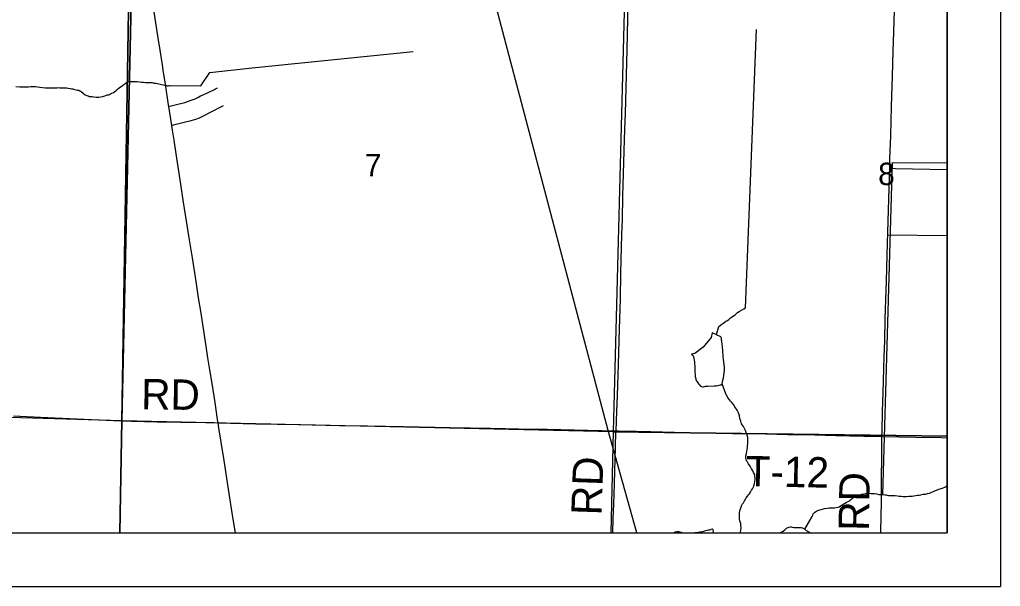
# Model space of a CAD drawing. Extents: x 0 to 34, y 0 to 22.
# Drawn here: x 7.163 to 9, y 14 to 15.061 of the extents above; entities that cross this region are included whole.
import ezdxf

# ---------------------------------------------------------------- set-up
doc = ezdxf.new("R2010")
doc.units = 0
for name, color, linetype in [('Default', 7, 'Continuous'), ('GM_X_Minor_Lake', 7, 'Continuous'), ('GM_X_Minor_River', 7, 'Continuous'), ('GM_X_Rail_Line', 7, 'Continuous'), ('GM_X_Section', 7, 'Continuous'), ('GM_X_Section_Text', 7, 'Continuous'), ('GM_X_State_Route', 7, 'Continuous'), ('GM_X_Township_Road', 7, 'Continuous'), ('GM_X_Township_Road_Text', 7, 'Continuous'), ('SH_Data', 7, 'Continuous')]:
    doc.layers.add(name, color=color, linetype=linetype)

msp = doc.modelspace()

# ---------------------------------------------------------------- linework, layer by layer
at = {"layer": 'Default'}
for points in [[(8.9, 14.2811), (8.9, 15.2832), (8.3007, 15.2901), (8.2749, 14.2894)], [(8.2702, 14.1), (8.9, 14.1), (8.9, 14.2811), (8.2749, 14.2894)]]:
    msp.add_lwpolyline(points, close=True, dxfattribs=at)
at = {"layer": 'GM_X_Minor_Lake'}
for points in [[(8.46, 14.4747), (8.4583, 14.4656), (8.4431, 14.4481), (8.4279, 14.4362), (8.4214, 14.4345), (8.4241, 14.4329), (8.4251, 14.4294), (8.4258, 14.4264), (8.4261, 14.4233), (8.4269, 14.4206), (8.4268, 14.4183), (8.4271, 14.4164), (8.4274, 14.413), (8.4274, 14.4096), (8.4273, 14.4065), (8.4276, 14.4039), (8.4279, 14.4008), (8.4282, 14.3962), (8.4285, 14.3924), (8.4292, 14.3894), (8.4296, 14.3871), (8.4299, 14.3851), (8.4321, 14.3828), (8.4343, 14.379), (8.4362, 14.3774), (8.4377, 14.3755), (8.4399, 14.3743), (8.4418, 14.3735), (8.4441, 14.3738), (8.4476, 14.3745), (8.4518, 14.3748), (8.464, 14.3752)], [(8.46, 14.4747), (8.4583, 14.4656), (8.4431, 14.4481), (8.4279, 14.4362), (8.4214, 14.4345), (8.4241, 14.4329), (8.4251, 14.4294), (8.4258, 14.4264), (8.4261, 14.4233), (8.4269, 14.4206), (8.4268, 14.4183), (8.4271, 14.4164), (8.4274, 14.413), (8.4274, 14.4096), (8.4273, 14.4065), (8.4276, 14.4039), (8.4279, 14.4008), (8.4282, 14.3962), (8.4285, 14.3924), (8.4292, 14.3894), (8.4296, 14.3871), (8.4299, 14.3851), (8.4321, 14.3828), (8.4343, 14.379), (8.4362, 14.3774), (8.4377, 14.3755), (8.4399, 14.3743), (8.4418, 14.3735), (8.4441, 14.3738), (8.4476, 14.3745), (8.4518, 14.3748), (8.464, 14.3752), (8.4678, 14.3755), (8.4712, 14.3758), (8.4735, 14.3766), (8.4762, 14.3773), (8.4785, 14.3791), (8.4798, 14.3863), (8.481, 14.3905), (8.4819, 14.395), (8.4824, 14.4003), (8.4829, 14.4045), (8.483, 14.4095), (8.4827, 14.4152), (8.482, 14.4198), (8.4814, 14.4251), (8.4808, 14.4305), (8.4805, 14.435), (8.4802, 14.4385), (8.4798, 14.4411), (8.4799, 14.4434), (8.4796, 14.4457), (8.4796, 14.448), (8.4793, 14.4503), (8.4789, 14.4526), (8.4786, 14.4549), (8.4783, 14.4572), (8.4779, 14.4591), (8.4776, 14.461), (8.4776, 14.4629), (8.4773, 14.4648), (8.4766, 14.4671), (8.46, 14.4747)], [(8.464, 14.3752), (8.4678, 14.3755), (8.4712, 14.3758), (8.4735, 14.3766), (8.4762, 14.3773), (8.4785, 14.3791), (8.4798, 14.3863), (8.481, 14.3905), (8.4819, 14.395), (8.4824, 14.4003), (8.4829, 14.4045), (8.483, 14.4095), (8.4827, 14.4152), (8.482, 14.4198), (8.4814, 14.4251), (8.4808, 14.4305), (8.4805, 14.435), (8.4802, 14.4385), (8.4798, 14.4411), (8.4799, 14.4434), (8.4796, 14.4457), (8.4796, 14.448), (8.4793, 14.4503), (8.4789, 14.4526), (8.4786, 14.4549), (8.4783, 14.4572), (8.4779, 14.4591), (8.4776, 14.461), (8.4776, 14.4629), (8.4773, 14.4648), (8.4766, 14.4671), (8.46, 14.4747)], [(8.3881, 14.1), (8.3884, 14.1005), (8.3907, 14.102), (8.3938, 14.1027), (8.3968, 14.1026), (8.3991, 14.1022), (8.4021, 14.1014), (8.4047, 14.1)], [(8.4618, 14.1), (8.4619, 14.1004), (8.4623, 14.1035), (8.462, 14.1061), (8.4601, 14.1069), (8.4574, 14.1062), (8.4548, 14.1055), (8.4529, 14.1052), (8.4509, 14.1045), (8.4483, 14.1038), (8.4456, 14.1031), (8.4437, 14.1027), (8.4417, 14.1024), (8.4391, 14.1017), (8.4368, 14.1014), (8.4337, 14.1007), (8.4299, 14.1004), (8.4278, 14.1)]]:
    msp.add_lwpolyline(points, dxfattribs=at)
at = {"layer": 'GM_X_Minor_River'}
msp.add_line((8.7886, 14.6579), (8.9, 14.6566), dxfattribs=at)
for points in [[(8.5226, 14.5216), (8.5433, 15.0424)], [(7.4448, 14.9375), (7.5023, 14.937), (7.5192, 14.9621), (7.5986, 14.9706), (7.9, 15.0012)], [(7.2774, 14.9271), (7.2822, 14.9224), (7.2856, 14.9201), (7.2886, 14.9189), (7.2913, 14.918), (7.2932, 14.9172), (7.2958, 14.9172), (7.2985, 14.9171), (7.3019, 14.9167), (7.3061, 14.9158), (7.311, 14.9157), (7.3141, 14.9164), (7.3187, 14.9171), (7.3221, 14.9185), (7.3244, 14.9192), (7.3267, 14.9199), (7.329, 14.9203), (7.3309, 14.921), (7.3332, 14.9221), (7.3356, 14.9232), (7.3383, 14.9246), (7.341, 14.9265), (7.3433, 14.9283), (7.346, 14.9309), (7.3495, 14.9335), (7.3518, 14.9354), (7.3549, 14.9368), (7.358, 14.9394), (7.3615, 14.942), (7.3634, 14.9439), (7.3676, 14.9449), (7.3714, 14.9452), (7.3749, 14.9451), (7.3775, 14.9451), (7.3798, 14.945), (7.3832, 14.9449), (7.387, 14.9445), (7.3912, 14.944), (7.395, 14.9439), (7.3984, 14.9435), (7.4019, 14.9434), (7.4068, 14.9433), (7.411, 14.9432), (7.4148, 14.9423), (7.4182, 14.9423), (7.4209, 14.9414), (7.4288, 14.9397), (7.4315, 14.9389), (7.4345, 14.9385), (7.4368, 14.938), (7.4394, 14.9372), (7.4417, 14.9372), (7.4433, 14.9375), (7.4448, 14.9375)], [(7.1557, 14.9355), (7.1629, 14.9354), (7.1683, 14.9352), (7.174, 14.9351), (7.1793, 14.9354), (7.1835, 14.9357), (7.1877, 14.936), (7.1923, 14.9355), (7.1964, 14.935), (7.2006, 14.9345), (7.2055, 14.9337), (7.2109, 14.9332), (7.2162, 14.933), (7.22, 14.9333), (7.2246, 14.9332), (7.2291, 14.9331), (7.233, 14.9334), (7.2353, 14.9338), (7.2379, 14.9333), (7.241, 14.9332), (7.244, 14.9332), (7.2474, 14.9331), (7.2512, 14.933), (7.2539, 14.9326), (7.2573, 14.9321), (7.26, 14.9317), (7.2626, 14.9312), (7.2656, 14.93), (7.2687, 14.9296), (7.2713, 14.9291), (7.2736, 14.9287), (7.2755, 14.9279), (7.2774, 14.9271)], [(8.7795, 14.1721), (8.7977, 14.7937), (8.9, 14.7928)], [(8.468, 14.4716), (8.4728, 14.4866), (8.4779, 14.4907), (8.4821, 14.4936), (8.4856, 14.4962), (8.4887, 14.498), (8.4914, 14.4999), (8.4945, 14.5025), (8.4976, 14.5047), (8.4999, 14.5065), (8.5034, 14.5084), (8.5053, 14.5102), (8.5076, 14.5125), (8.5107, 14.5147), (8.5196, 14.5194), (8.5223, 14.5213), (8.5226, 14.5216)], [(8.513, 14.1), (8.5133, 14.1012), (8.5142, 14.1091), (8.514, 14.1149), (8.5137, 14.1179), (8.5126, 14.121), (8.5119, 14.1229), (8.5112, 14.1267), (8.5113, 14.1305), (8.5114, 14.1343), (8.5114, 14.1374), (8.5119, 14.1412), (8.5131, 14.145), (8.5151, 14.1506), (8.5171, 14.1544), (8.5187, 14.1563), (8.5207, 14.16), (8.5219, 14.1623), (8.5238, 14.1657), (8.5262, 14.1686), (8.5281, 14.1713), (8.5301, 14.1735), (8.5317, 14.1765), (8.5337, 14.1799), (8.5356, 14.1825), (8.5368, 14.1848), (8.538, 14.1874), (8.5388, 14.1897), (8.5393, 14.1923), (8.5397, 14.1961), (8.5406, 14.1999), (8.5403, 14.2079), (8.5396, 14.2098), (8.5378, 14.2129), (8.5363, 14.216), (8.5338, 14.2203), (8.5312, 14.2253), (8.5282, 14.2295), (8.526, 14.233), (8.5246, 14.2353), (8.5235, 14.2384), (8.5232, 14.2414), (8.5232, 14.2445), (8.5241, 14.249), (8.5249, 14.2524), (8.5258, 14.2562), (8.5262, 14.2596), (8.5263, 14.2634), (8.5268, 14.2669), (8.5272, 14.2699), (8.5269, 14.2733), (8.5266, 14.2779), (8.5256, 14.2836), (8.5238, 14.2882), (8.5223, 14.2921), (8.5205, 14.2955), (8.5187, 14.299), (8.5168, 14.3017), (8.515, 14.3044), (8.5136, 14.3094), (8.5122, 14.3144), (8.5111, 14.319), (8.5093, 14.3247), (8.5068, 14.3301), (8.5027, 14.3359), (8.4998, 14.3406), (8.4972, 14.344), (8.4946, 14.3468), (8.4927, 14.3491), (8.4909, 14.3514), (8.4894, 14.3534), (8.4868, 14.358), (8.4854, 14.3607), (8.4785, 14.3791)], [(8.6334, 14.1068), (8.6472, 14.1305), (8.6484, 14.1332), (8.6492, 14.1358), (8.6516, 14.138), (8.6543, 14.1399), (8.6581, 14.1421), (8.662, 14.1431), (8.6666, 14.1445), (8.6708, 14.1456), (8.6754, 14.1463), (8.6792, 14.1469), (8.6818, 14.1469), (8.6845, 14.1468), (8.6868, 14.1468), (8.6895, 14.1471), (8.6925, 14.1474), (8.6952, 14.1481), (8.6979, 14.1492), (8.7006, 14.1506), (8.7029, 14.1521), (8.7052, 14.1536), (8.7079, 14.155), (8.711, 14.1569), (8.7133, 14.1583), (8.716, 14.1594), (8.7179, 14.1609), (8.7199, 14.1624), (8.7218, 14.1639), (8.7238, 14.1657), (8.7257, 14.1672), (8.7276, 14.1687), (8.7295, 14.1694), (8.7326, 14.1705), (8.7349, 14.1712), (8.7384, 14.1719), (8.7403, 14.1726), (8.7475, 14.1736), (8.7502, 14.1739), (8.754, 14.1742), (8.7571, 14.1741), (8.7601, 14.174), (8.7639, 14.1736), (8.7677, 14.1731), (8.7726, 14.1722), (8.7795, 14.1721), (8.7833, 14.1716), (8.7859, 14.1715), (8.7882, 14.1707), (8.7901, 14.1703), (8.7935, 14.1702), (8.7977, 14.1701), (8.8027, 14.17), (8.8072, 14.1692), (8.8106, 14.1687), (8.8141, 14.1686), (8.8179, 14.1682), (8.8209, 14.1681), (8.8243, 14.1684), (8.8285, 14.1687), (8.832, 14.1686), (8.835, 14.1689), (8.8377, 14.1696), (8.8415, 14.1703), (8.8446, 14.1706), (8.8476, 14.1709), (8.8511, 14.1716), (8.8553, 14.1723), (8.8576, 14.1726), (8.8599, 14.1729), (8.8633, 14.1736), (8.8675, 14.1747), (8.8717, 14.1765), (8.8775, 14.179), (8.8848, 14.1819), (8.8917, 14.184), (8.8971, 14.1866), (8.9, 14.188)], [(8.5874, 14.1), (8.5883, 14.101), (8.5929, 14.1036), (8.596, 14.1058), (8.5995, 14.1087), (8.6034, 14.1106), (8.6064, 14.1113), (8.6083, 14.1112), (8.6102, 14.1108), (8.6129, 14.1103), (8.6156, 14.1103), (8.6178, 14.1102), (8.6205, 14.1102), (8.6239, 14.1101), (8.627, 14.11), (8.6293, 14.1096), (8.6334, 14.1068), (8.6364, 14.1049), (8.6398, 14.1029), (8.6428, 14.1009), (8.6436, 14.1)]]:
    msp.add_lwpolyline(points, dxfattribs=at)
at = {"layer": 'GM_X_Rail_Line'}
msp.add_lwpolyline([(8.3191, 14.1), (8.2652, 14.2915), (7.9984, 15.3006), (7.7787, 16.1186), (7.5464, 16.952), (7.4475, 17.3725), (7.3986, 17.4999), (7.3389, 17.6382), (7.2697, 17.7778), (7.0716, 18.0894), (7.0417, 18.1342), (7.0105, 18.1626), (6.978, 18.1748), (6.9427, 18.181)], dxfattribs=at)
at = {"layer": 'GM_X_Section'}
for points in [[(6.3631, 15.3454), (7.3704, 15.3088), (7.3544, 14.3098), (6.3444, 14.34)], [(7.3704, 15.3088), (8.3007, 15.2901), (8.2749, 14.2894), (7.3544, 14.3098)]]:
    msp.add_lwpolyline(points, close=True, dxfattribs=at)
at = {"layer": 'GM_X_State_Route'}
msp.add_lwpolyline([(7.4137, 15.0791), (7.4213, 15.0306), (7.4251, 15.0035), (7.4295, 14.9765), (7.4317, 14.9618), (7.4352, 14.9403), (7.4412, 14.9016), (7.4417, 14.8983), (7.4471, 14.8629), (7.4484, 14.8543), (7.4514, 14.8352), (7.4551, 14.81), (7.4642, 14.7529), (7.4687, 14.7228), (7.4761, 14.6761), (7.4798, 14.6522), (7.4858, 14.6153), (7.4928, 14.5705), (7.4974, 14.5404), (7.5016, 14.5153), (7.5115, 14.4495), (7.5148, 14.428), (7.5183, 14.4053), (7.5226, 14.3795), (7.5282, 14.3445), (7.533, 14.3125), (7.5339, 14.3064), (7.5353, 14.2965), (7.5396, 14.2702), (7.545, 14.2358), (7.5536, 14.1817), (7.5616, 14.1295), (7.5663, 14.1)], dxfattribs=at)
at = {"layer": 'GM_X_Township_Road'}
for points in [[(2.1, 18.4074), (2.1, 14.1), (7.3507, 14.1), (7.3542, 14.3107), (7.3767, 15.3155), (7.3854, 16.3696)], [(8.28, 14.2912), (8.2817, 14.3279), (8.2828, 14.3575), (8.2846, 14.4162), (8.2866, 14.4821), (8.2881, 14.5374), (8.2892, 14.5877), (8.2899, 14.6107), (8.291, 14.6586), (8.2919, 14.6871), (8.293, 14.7313), (8.2935, 14.7511), (8.2953, 14.8151), (8.2967, 14.8561), (8.2975, 14.8854), (8.2995, 14.9574), (8.3006, 15.0047), (8.3029, 15.0923), (8.3038, 15.1389), (8.3043, 15.1675), (8.3053, 15.2079), (8.3058, 15.2402), (8.3066, 15.2669), (8.3073, 15.2949)], [(8.7928, 14.7829), (8.7932, 14.8005), (8.7947, 14.8434), (8.7963, 14.8981), (8.7979, 14.9552), (8.7992, 15.0018), (8.8001, 15.0379), (8.802, 15.0981), (8.8031, 15.1366), (8.8048, 15.1919), (8.8068, 15.2559), (8.8077, 15.2857)], [(7.4417, 14.8983), (7.454, 14.9013), (7.4722, 14.9061), (7.4839, 14.9101), (7.4914, 14.913), (7.4965, 14.9152), (7.5017, 14.918), (7.5066, 14.9203), (7.5148, 14.9242), (7.5275, 14.9304), (7.5297, 14.9315), (7.5336, 14.9332)], [(7.4471, 14.8629), (7.456, 14.8653), (7.4712, 14.8688), (7.4843, 14.8724), (7.4927, 14.8748), (7.4995, 14.8772), (7.5082, 14.8813), (7.5202, 14.8878), (7.5444, 14.9005)], [(8.7781, 14.2807), (8.7784, 14.2905), (8.7792, 14.3271), (8.7802, 14.3632), (8.7822, 14.4296), (8.7833, 14.4601), (8.7843, 14.5011), (8.7866, 14.5713), (8.788, 14.6204), (8.7893, 14.6632), (8.7924, 14.7667), (8.7928, 14.7829)], [(8.7928, 14.7829), (8.7977, 14.7827), (8.8033, 14.7824), (8.8996, 14.7805), (8.9, 14.7805)], [(7.1511, 14.3193), (7.202, 14.317), (7.325, 14.3114), (7.3534, 14.3102)], [(7.3534, 14.3102), (7.3544, 14.3102), (7.3722, 14.3094), (7.4201, 14.3083), (7.4648, 14.3073), (7.5115, 14.3066), (7.527, 14.3065), (7.5339, 14.3064)], [(7.5339, 14.3064), (7.605, 14.3042), (7.6852, 14.3029), (7.7622, 14.3014), (7.8145, 14.3005), (7.8822, 14.299), (7.9692, 14.2976), (8.0451, 14.2961), (8.073, 14.2955), (8.0973, 14.2949), (8.1507, 14.2942), (8.2272, 14.2924), (8.28, 14.2912)], [(8.2737, 14.1), (8.2738, 14.1025), (8.2746, 14.1255), (8.2759, 14.1547), (8.2764, 14.1727), (8.2769, 14.1926), (8.2792, 14.2615), (8.2799, 14.2895), (8.28, 14.2912)], [(8.28, 14.2912), (8.285, 14.2911), (8.3111, 14.2907), (8.3186, 14.2905), (8.3453, 14.2899), (8.3894, 14.2886), (8.4714, 14.2869), (8.4988, 14.2863), (8.5311, 14.2859), (8.5609, 14.2854), (8.6013, 14.2844), (8.6523, 14.2834), (8.6915, 14.2824), (8.7443, 14.2814), (8.7707, 14.2809), (8.7781, 14.2807)], [(8.7761, 14.1), (8.7762, 14.1036), (8.7774, 14.1589), (8.7773, 14.1968), (8.7778, 14.2477), (8.778, 14.267), (8.7781, 14.2807)], [(8.7781, 14.2807), (8.8413, 14.2792), (8.8897, 14.2784), (8.9, 14.2782)]]:
    msp.add_lwpolyline(points, dxfattribs=at)
msp.add_lwpolyline([(7.3507, 14.1), (8.9, 14.1), (8.9, 16.335), (8.8983, 16.335), (8.8568, 16.3357), (8.8514, 16.3359), (8.8195, 16.3375), (8.3316, 16.3505), (7.3854, 16.3696), (7.3767, 15.3155), (7.3542, 14.3107)], close=True, dxfattribs=at)
at = {"layer": 'SH_Data'}
for p, q in [((9, 21), (9, 14)), ((8.9, 20.9), (8.9, 14.1)), ((2.1, 14.1), (8.9, 14.1)), ((2, 14), (9, 14))]:
    msp.add_line(p, q, dxfattribs=at)

# ---------------------------------------------------------------- texts
at = {"layer": 'GM_X_Section_Text'}
for s, p in [('7', (7.8093, 14.7675)), ('8', (8.771, 14.7512))]:
    msp.add_text(s, height=0.0419, rotation=0, dxfattribs=at).set_placement(p)
at = {"layer": 'GM_X_Township_Road_Text'}
for s, rotation, p in [('RD', 359.0223, (7.3901, 14.3318)), ('RD', 88.0398, (8.2528, 14.1324)), ('T-12', 358.9577, (8.5224, 14.1875)), ('RD', 89.036, (8.7536, 14.1036))]:
    msp.add_text(s, height=0.05682, rotation=rotation, dxfattribs=at).set_placement(p)

doc.saveas('drawing.dxf')
